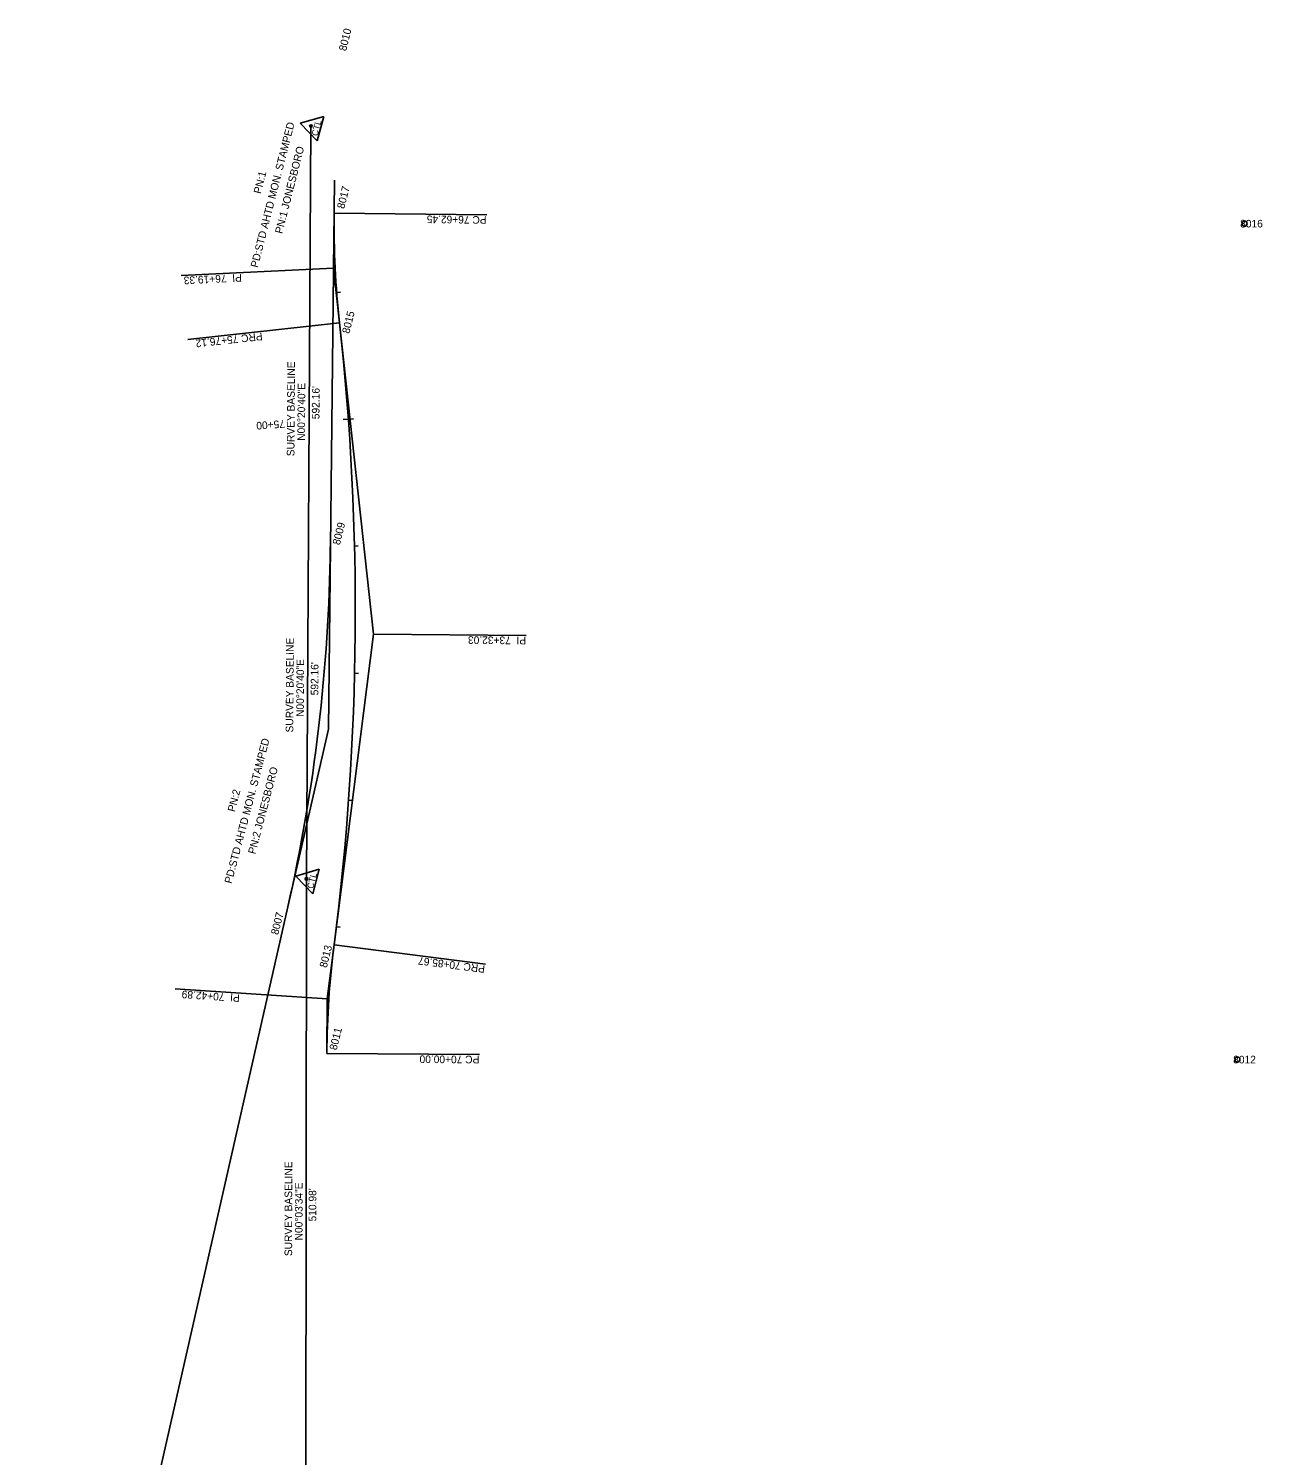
# Model space of a CAD drawing. Extents: x 1710417 to 1716352, y 548603 to 551217.
# Drawn here: x 1712247 to 1713217, y 550094 to 551217 of the extents above; entities that cross this region are included whole.
import ezdxf

# ---------------------------------------------------------------- set-up
doc = ezdxf.new("R2010")
doc.units = 0
for name, color, linetype in [('G-ANNO-TEXT', 7, 'Continuous'), ('R_Horz Alg', 7, 'Continuous'), ('R_Horz Alg Annot', 7, 'Continuous'), ('S_BASELINE', 7, 'Continuous'), ('S_BASELINE_ANNOT', 7, 'Continuous'), ('S_PRIMARY_CTL_ANNOT', 7, 'Continuous')]:
    doc.layers.add(name, color=color, linetype=linetype)

msp = doc.modelspace()

# ---------------------------------------------------------------- linework, layer by layer
at = {"layer": 'G-ANNO-TEXT'}
for p, q in [((1712460.5, 551142.2), (1712479, 551147.5)), ((1712473.9, 551128.3), (1712479, 551147.5)), ((1712460.5, 551142.2), (1712473.9, 551128.3)), ((1712456.9, 550550), (1712475.4, 550555.4)), ((1712470.5, 550536.2), (1712475.4, 550555.4)), ((1712456.9, 550550), (1712470.5, 550536.2))]:
    msp.add_line(p, q, dxfattribs=at)
for centre, radius in [((1712468.9, 551140), 1.04), ((1712468.9, 551140), 0.609), ((1712468.9, 551140), 0.344), ((1712465.4, 550547.8), 1.04), ((1712465.4, 550547.8), 0.609), ((1712465.4, 550547.8), 0.344)]:
    msp.add_circle(centre, radius, dxfattribs=at)
at = {"layer": 'R_Horz Alg'}
for p, q in [((1712484.2, 550809.1), (1712487.5, 551097.3)), ((1712246.8, 549627.3), (1712450.8, 550525.8))]:
    msp.add_line(p, q, dxfattribs=at)
for centre, radius, start, end in [((1713203.3, 551063.2), 716.2, 179.3424, 186.2485), ((1710420.3, 550758.5), 2083.5, 352.7611, 6.2485), ((1711136.1, 550824.3), 1348.1, 347.2066, 359.3498), ((1713197.6, 550405.7), 716.2, 172.7611, 179.6146)]:
    msp.add_arc(centre, radius, start, end, dxfattribs=at)
at = {"layer": 'R_Horz Alg Annot'}
for p, q in [((1712486.7, 551028.2), (1712487.2, 551071.4)), ((1712491.4, 550985.3), (1712486.7, 551028.2)), ((1712518.2, 550740.4), (1712491.4, 550985.3)), ((1712482.6, 550665.7), (1712484.2, 550809.1)), ((1712487.1, 550496), (1712518.2, 550740.4)), ((1712450.8, 550525.8), (1712482.6, 550665.7)), ((1712481.7, 550453.4), (1712487.1, 550496)), ((1712481.5, 550410.5), (1712481.7, 550453.4))]:
    msp.add_line(p, q, dxfattribs=at)
for points in [[(1712487.2, 551071.4), (1712607.2, 551070.1)], [(1712486.7, 551028.2), (1712366.8, 551022.4)], [(1712492.2, 551009.3), (1712489.2, 551009)], [(1712491.4, 550985.3), (1712372.1, 550972.2)], [(1712494.3, 550909.2), (1712502.3, 550909.7)], [(1712506.1, 550809.7), (1712503.1, 550809.6)], [(1712518.2, 550740.4), (1712638.2, 550739.3)], [(1712506.2, 550709.5), (1712503.2, 550709.6)], [(1712501.4, 550609.5), (1712498.4, 550609.7)], [(1712491.9, 550509.8), (1712488.9, 550510.2)], [(1712487.1, 550496), (1712606.2, 550480.8)], [(1712481.7, 550453.4), (1712362, 550461.4)], [(1712481.5, 550410.5), (1712601.4, 550409.7)]]:
    msp.add_lwpolyline(points, dxfattribs=at)
for centre in [(1713203.3, 551063.2), (1713197.6, 550405.7)]:
    msp.add_circle(centre, 2, dxfattribs=at)
at = {"layer": 'S_BASELINE'}
for p, q in [((1712465.4, 550547.8), (1712468.9, 551140)), ((1712464.8, 550036.9), (1712465.4, 550547.8))]:
    msp.add_line(p, q, dxfattribs=at)

# ---------------------------------------------------------------- texts
at = {"layer": 'G-ANNO-TEXT'}
for rotation, p in [(75.2165, (1712474.1, 551131.8)), (75.7181, (1712470.6, 550539.7))]:
    msp.add_text('CTL', height=5, rotation=rotation, dxfattribs=at).set_placement(p)
at = {"layer": 'R_Horz Alg Annot'}
for s, rotation, p in [('8010', 75.9935, (1712496.5, 551198.6)), ('8017', 75.9935, (1712495.1, 551074.5)), ('PC 76+62.45', 179.3424, (1712607.1, 551069.1)), ('PI  76+19.33', 182.7954, (1712414.4, 551023.7)), ('8015', 75.9935, (1712499.1, 550976.3)), ('PRC 75+76.12', 186.2485, (1712430.5, 550977.6)), ('75+00', 184.1552, (1712448.2, 550908.8)), ('8009', 75.9935, (1712491.6, 550810.1)), ('PI  73+32.03', 179.5048, (1712638.2, 550738.3)), ('8007', 75.9935, (1712443.1, 550503.4)), ('8013', 75.9935, (1712481.3, 550477.5)), ('PRC 70+85.67', 172.7611, (1712606.1, 550479.8)), ('PI  70+42.89', 176.1878, (1712413.1, 550457)), ('8011', 75.9935, (1712489.1, 550412.7)), ('PC 70+00.00', 179.6146, (1712601.4, 550408.7))]:
    msp.add_text(s, height=6, rotation=rotation, dxfattribs=at).set_placement(p)
for s, p in [('8016', (1713199.8, 551060.2)), ('8012', (1713194.3, 550402.7))]:
    msp.add_text(s, height=6, dxfattribs=at).set_placement(p)
at = {"layer": 'S_BASELINE_ANNOT'}
for s, rotation, p in [('SURVEY BASELINE', 89.6556, (1712455.9, 550880.3)), ('N00%%d20\'40"E', 89.6556, (1712464.2, 550892.4)), ("592.16'", 89.6556, (1712475.6, 550909.4)), ('SURVEY BASELINE', 89.6556, (1712455, 550663)), ('N00%%d20\'40"E', 89.6556, (1712463.3, 550675.2)), ("592.16'", 89.6556, (1712474.7, 550692.2)), ('SURVEY BASELINE', 89.9407, (1712454.1, 550251.1)), ('N00%%d03\'34"E', 89.9407, (1712462.3, 550263.5)), ("510.98'", 89.9407, (1712473.1, 550278.4))]:
    msp.add_text(s, height=6, rotation=rotation, dxfattribs=at).set_placement(p)
at = {"layer": 'S_PRIMARY_CTL_ANNOT'}
for s, rotation, p in [('PD:STD AHTD MON. STAMPED', 75.732, (1712427.1, 551028.2)), ('PN:1 JONESBORO', 75.732, (1712446.3, 551054.9)), ('PN:1', 75.732, (1712429.5, 551086.3)), ('PD:STD AHTD MON. STAMPED', 75.2755, (1712406.5, 550543.7)), ('PN:2 JONESBORO', 75.2755, (1712425.1, 550566.9)), ('PN:2', 75.2755, (1712409, 550600.1))]:
    msp.add_text(s, height=6, rotation=rotation, dxfattribs=at).set_placement(p)

doc.saveas('drawing.dxf')
